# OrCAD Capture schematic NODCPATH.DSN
size A
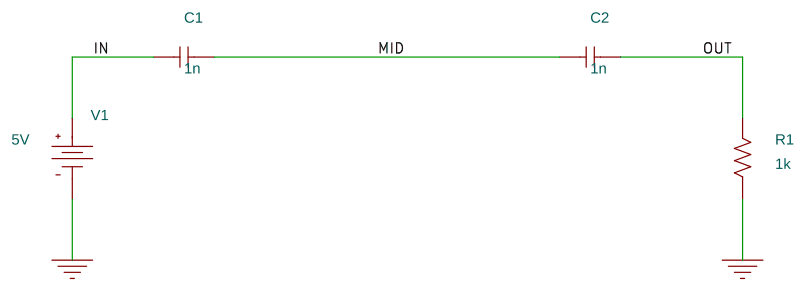
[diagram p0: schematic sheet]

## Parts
C1  1n  [RAD/CK05]
C2  1n  [RAD/CK05]
R1  1k  [AX/RC05]
V1  VDC

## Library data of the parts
C1 C2 = C
R1 = R
V1 = VDC: DC: 5V

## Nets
0: R1.1 V1.1(-)
IN: C1.1 V1.0(+)
MID: C1.2 C2.1
OUT: C2.2 R1.2
